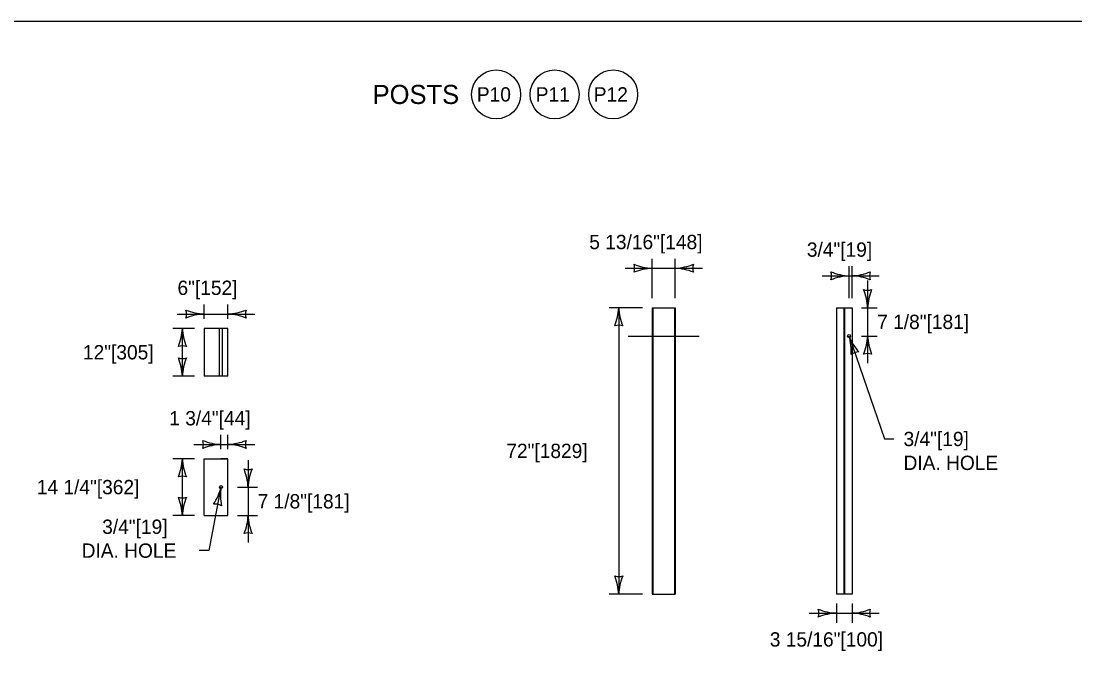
# Model space of a CAD drawing. Extents: x 49991 to 50160, y 49948 to 50051.
# Drawn here: x 50006.556 to 50010.973, y 49990.681 to 49993.358 of the extents above; entities that cross this region are included whole.
import ezdxf

# ---------------------------------------------------------------- set-up
doc = ezdxf.new("R2010")
doc.units = 0
for name, color, linetype in [('Level 1', 7, 'Continuous'), ('Level 2', 7, 'Continuous'), ('Level 3', 7, 'Continuous'), ('Level 4', 7, 'Continuous'), ('Level 5', 7, 'Continuous')]:
    doc.layers.add(name, color=color, linetype=linetype)

msp = doc.modelspace()

# ---------------------------------------------------------------- linework, layer by layer
at = {"layer": 'Level 1'}
for p, q in [((50009.2008, 49992.1569), (50009.2008, 49990.9569)), ((50009.2008, 49992.1569), (50009.2979, 49992.1569)), ((50009.204, 49992.1569), (50009.204, 49990.9569)), ((50009.2947, 49992.1569), (50009.2947, 49990.9569)), ((50009.2979, 49992.1569), (50009.2979, 49990.9569)), ((50009.973, 49992.1569), (50010.0387, 49992.1569)), ((50009.973, 49992.1569), (50009.973, 49990.9569)), ((50010.0387, 49992.1569), (50010.0387, 49990.9569)), ((50007.4228, 49992.0703), (50007.3228, 49992.0703)), ((50007.3228, 49992.0703), (50007.3228, 49991.8703)), ((50007.4228, 49991.8703), (50007.4228, 49992.0703)), ((50007.4228, 49991.8703), (50007.3228, 49991.8703)), ((50007.3228, 49991.2864), (50007.3228, 49991.5239)), ((50007.3228, 49991.5239), (50007.4228, 49991.5239)), ((50007.4228, 49991.5239), (50007.3936, 49991.5239)), ((50007.4228, 49991.2864), (50007.4228, 49991.5239)), ((50007.3228, 49991.2864), (50007.4228, 49991.2864)), ((50009.2008, 49990.9569), (50009.2979, 49990.9569)), ((50010.0387, 49990.9569), (50009.973, 49990.9569))]:
    msp.add_line(p, q, dxfattribs=at)
msp.add_lwpolyline([(50006.474, 49993.358), (50011.2031, 49993.358), (50011.2031, 49987.7988)], dxfattribs=at)
for centre in [(50010.0262, 49992.0382), (50007.3936, 49991.4051)]:
    msp.add_circle(centre, 0.00625, dxfattribs=at)
at = {"layer": 'Level 2'}
for centre in [(50008.5469, 49993.0506), (50008.7921, 49993.0506), (50009.0374, 49993.0506)]:
    msp.add_circle(centre, 0.1026, dxfattribs=at)
at = {"layer": 'Level 3'}
for p, q in [((50009.2008, 49992.1969), (50009.2008, 49992.3622)), ((50009.2979, 49992.1969), (50009.2979, 49992.3622)), ((50009.0873, 49992.3222), (50009.4114, 49992.3222)), ((50010.0262, 49992.1969), (50010.0262, 49992.3304)), ((50010.0387, 49992.1969), (50010.0387, 49992.3304)), ((50009.9128, 49992.2904), (50010.1522, 49992.2904)), ((50010.104, 49992.2704), (50010.104, 49991.9248)), ((50007.3228, 49992.1103), (50007.3228, 49992.1703)), ((50007.4228, 49992.1103), (50007.4228, 49992.1703)), ((50007.2094, 49992.1303), (50007.5362, 49992.1303)), ((50009.1608, 49992.1569), (50009.0208, 49992.1569)), ((50009.0608, 49992.1569), (50009.0608, 49990.9569)), ((50010.0787, 49992.1569), (50010.144, 49992.1569)), ((50007.2828, 49992.0703), (50007.1919, 49992.0703)), ((50007.2319, 49991.8703), (50007.2319, 49992.0703)), ((50010.0262, 49992.0382), (50010.1744, 49991.6068)), ((50010.0787, 49992.0382), (50010.144, 49992.0382)), ((50007.2828, 49991.8703), (50007.1919, 49991.8703)), ((50007.3936, 49991.5639), (50007.3936, 49991.6239)), ((50007.4228, 49991.5639), (50007.4228, 49991.6239)), ((50010.1744, 49991.6068), (50010.2144, 49991.6068)), ((50007.2802, 49991.5839), (50007.5362, 49991.5839)), ((50007.2828, 49991.5239), (50007.1919, 49991.5239)), ((50007.2319, 49991.2864), (50007.2319, 49991.5239)), ((50007.5073, 49991.5186), (50007.5073, 49991.1729)), ((50007.3936, 49991.4051), (50007.3423, 49991.139)), ((50007.4628, 49991.4051), (50007.5473, 49991.4051)), ((50007.2828, 49991.2864), (50007.1919, 49991.2864)), ((50007.4628, 49991.2864), (50007.5473, 49991.2864)), ((50007.3423, 49991.139), (50007.3023, 49991.139)), ((50009.1608, 49990.9569), (50009.0208, 49990.9569)), ((50009.973, 49990.9169), (50009.973, 49990.8369)), ((50010.0387, 49990.9169), (50010.0387, 49990.8369)), ((50009.8596, 49990.8769), (50010.1522, 49990.8769))]:
    msp.add_line(p, q, dxfattribs=at)
for centre, radius, start, end in [((50009.2099, 49992.5444), 0.2223, 247.456, 267.6395), ((50009.0726, 49992.3222), 0.0548, 342.1388, 17.8612), ((50009.2123, 49992.0895), 0.233, 92.8273, 112.0772), ((50009.2864, 49992.555), 0.233, 272.8273, 292.0772), ((50009.2888, 49992.1001), 0.2223, 67.456, 87.6395), ((50009.4261, 49992.3222), 0.0548, 162.1388, 197.8612), ((50010.0354, 49992.5126), 0.2223, 247.456, 267.6395), ((50009.898, 49992.2904), 0.0548, 342.1388, 17.8612), ((50010.0272, 49992.5232), 0.233, 272.8273, 292.0772), ((50010.1669, 49992.2904), 0.0548, 162.1388, 197.8612), ((50010.0377, 49992.0577), 0.233, 92.8273, 112.0772), ((50010.0296, 49992.0683), 0.2223, 67.456, 87.6395), ((50010.104, 49992.2852), 0.0548, 252.1388, 287.8612), ((50009.8713, 49992.1455), 0.233, 2.8273, 22.0772), ((50010.3261, 49992.1478), 0.2223, 157.456, 177.6395), ((50007.3319, 49992.3525), 0.2223, 247.456, 267.6395), ((50007.1946, 49992.1303), 0.0548, 342.1388, 17.8612), ((50007.3343, 49991.8976), 0.233, 92.8273, 112.0772), ((50007.4113, 49992.363), 0.233, 272.8273, 292.0772), ((50007.4136, 49991.9082), 0.2223, 67.456, 87.6395), ((50007.551, 49992.1303), 0.0548, 162.1388, 197.8612), ((50008.8386, 49992.1661), 0.2223, 337.456, 357.6395), ((50009.2935, 49992.1684), 0.233, 182.8273, 202.0772), ((50009.0608, 49992.0287), 0.0548, 72.1388, 107.8612), ((50007.0098, 49992.0795), 0.2223, 337.456, 357.6395), ((50007.4646, 49992.0818), 0.233, 182.8273, 202.0772), ((50009.8131, 49991.9747), 0.2223, 356.4073, 16.5908), ((50010.2426, 49992.1246), 0.233, 201.7786, 221.0285), ((50009.8818, 49992.0474), 0.2223, 337.456, 357.6395), ((50010.3367, 49992.0497), 0.233, 182.8273, 202.0772), ((50007.2319, 49991.9421), 0.0548, 72.1388, 107.8612), ((50010.0679, 49991.9169), 0.0548, 91.0901, 126.8125), ((50010.104, 49991.91), 0.0548, 72.1388, 107.8612), ((50007.2319, 49991.9985), 0.0548, 252.1388, 287.8612), ((50006.9992, 49991.8588), 0.233, 2.8273, 22.0772), ((50007.454, 49991.8612), 0.2223, 157.456, 177.6395), ((50007.4028, 49991.806), 0.2223, 247.456, 267.6395), ((50007.2654, 49991.5839), 0.0548, 342.1388, 17.8612), ((50007.4113, 49991.8166), 0.233, 272.8273, 292.0772), ((50007.551, 49991.5839), 0.0548, 162.1388, 197.8612), ((50007.4051, 49991.3512), 0.233, 92.8273, 112.0772), ((50007.4136, 49991.3617), 0.2223, 67.456, 87.6395), ((50007.0098, 49991.533), 0.2223, 337.456, 357.6395), ((50007.4646, 49991.5354), 0.233, 182.8273, 202.0772), ((50007.5073, 49991.5333), 0.0548, 252.1388, 287.8612), ((50007.2746, 49991.3936), 0.233, 2.8273, 22.0772), ((50007.7295, 49991.396), 0.2223, 157.456, 177.6395), ((50007.2319, 49991.3957), 0.0548, 72.1388, 107.8612), ((50007.1772, 49991.4562), 0.2223, 326.5442, 346.7277), ((50007.6243, 49991.3724), 0.233, 171.9155, 191.1654), ((50007.2319, 49991.4146), 0.0548, 252.1388, 287.8612), ((50006.9992, 49991.2749), 0.233, 2.8273, 22.0772), ((50007.454, 49991.2772), 0.2223, 157.456, 177.6395), ((50007.3694, 49991.2792), 0.0548, 61.227, 96.9494), ((50007.2852, 49991.2955), 0.2223, 337.456, 357.6395), ((50007.74, 49991.2979), 0.233, 182.8273, 202.0772), ((50007.5073, 49991.1582), 0.0548, 72.1388, 107.8612), ((50009.0608, 49991.0852), 0.0548, 252.1388, 287.8612), ((50008.8281, 49990.9455), 0.233, 2.8273, 22.0772), ((50009.2829, 49990.9478), 0.2223, 157.456, 177.6395), ((50009.9822, 49991.0991), 0.2223, 247.456, 267.6395), ((50009.8448, 49990.8769), 0.0548, 342.1388, 17.8612), ((50010.0272, 49991.1097), 0.233, 272.8273, 292.0772), ((50010.1669, 49990.8769), 0.0548, 162.1388, 197.8612), ((50009.9845, 49990.6442), 0.233, 92.8273, 112.0772), ((50010.0296, 49990.6548), 0.2223, 67.456, 87.6395)]:
    msp.add_arc(centre, radius, start, end, dxfattribs=at)
at = {"layer": 'Level 4'}
for p, q in [((50010.0045, 49992.1569), (50010.0045, 49990.9569)), ((50010.0073, 49992.1569), (50010.0073, 49990.9569)), ((50007.3874, 49991.8703), (50007.3874, 49992.0703)), ((50007.3999, 49991.8703), (50007.3999, 49992.0703))]:
    msp.add_line(p, q, dxfattribs=at)
at = {"layer": 'Level 5'}
msp.add_line((50009.1008, 49992.0382), (50009.3979, 49992.0382), dxfattribs=at)

# ---------------------------------------------------------------- texts
at = {"layer": 'Level 2'}
for s, height, p in [('POSTS', 0.08, (50008.0292, 49993.0106)), ('P10', 0.06, (50008.4662, 49993.0208)), ('P11', 0.06, (50008.713, 49993.0209)), ('P12', 0.06, (50008.9562, 49993.0209)), ('5 13/16"[148]', 0.06, (50008.9373, 49992.4022)), ('3/4"[19]', 0.06, (50009.8492, 49992.3704)), ('6"[152]', 0.06, (50007.2113, 49992.2103)), ('7 1/8"[181]', 0.06, (50010.144, 49992.0676)), ('12"[305]', 0.06, (50006.8151, 49991.9403)), ('1 3/4"[44]', 0.06, (50007.177, 49991.6639)), ('3/4"[19]', 0.06, (50010.2544, 49991.5768)), ('72"[1829]', 0.06, (50008.5896, 49991.5269)), ('DIA. HOLE', 0.06, (50010.2544, 49991.4768)), ('14 1/4"[362]', 0.06, (50006.6217, 49991.3751)), ('7 1/8"[181]', 0.06, (50007.5473, 49991.3157)), ('3/4"[19]', 0.06, (50006.8958, 49991.209)), ('DIA. HOLE', 0.06, (50006.8097, 49991.109)), ('3 15/16"[100]', 0.06, (50009.6938, 49990.7369))]:
    msp.add_text(s, height=height, dxfattribs=at).set_placement(p)

doc.saveas('drawing.dxf')
